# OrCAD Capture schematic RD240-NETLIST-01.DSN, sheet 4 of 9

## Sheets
4 6: size A3
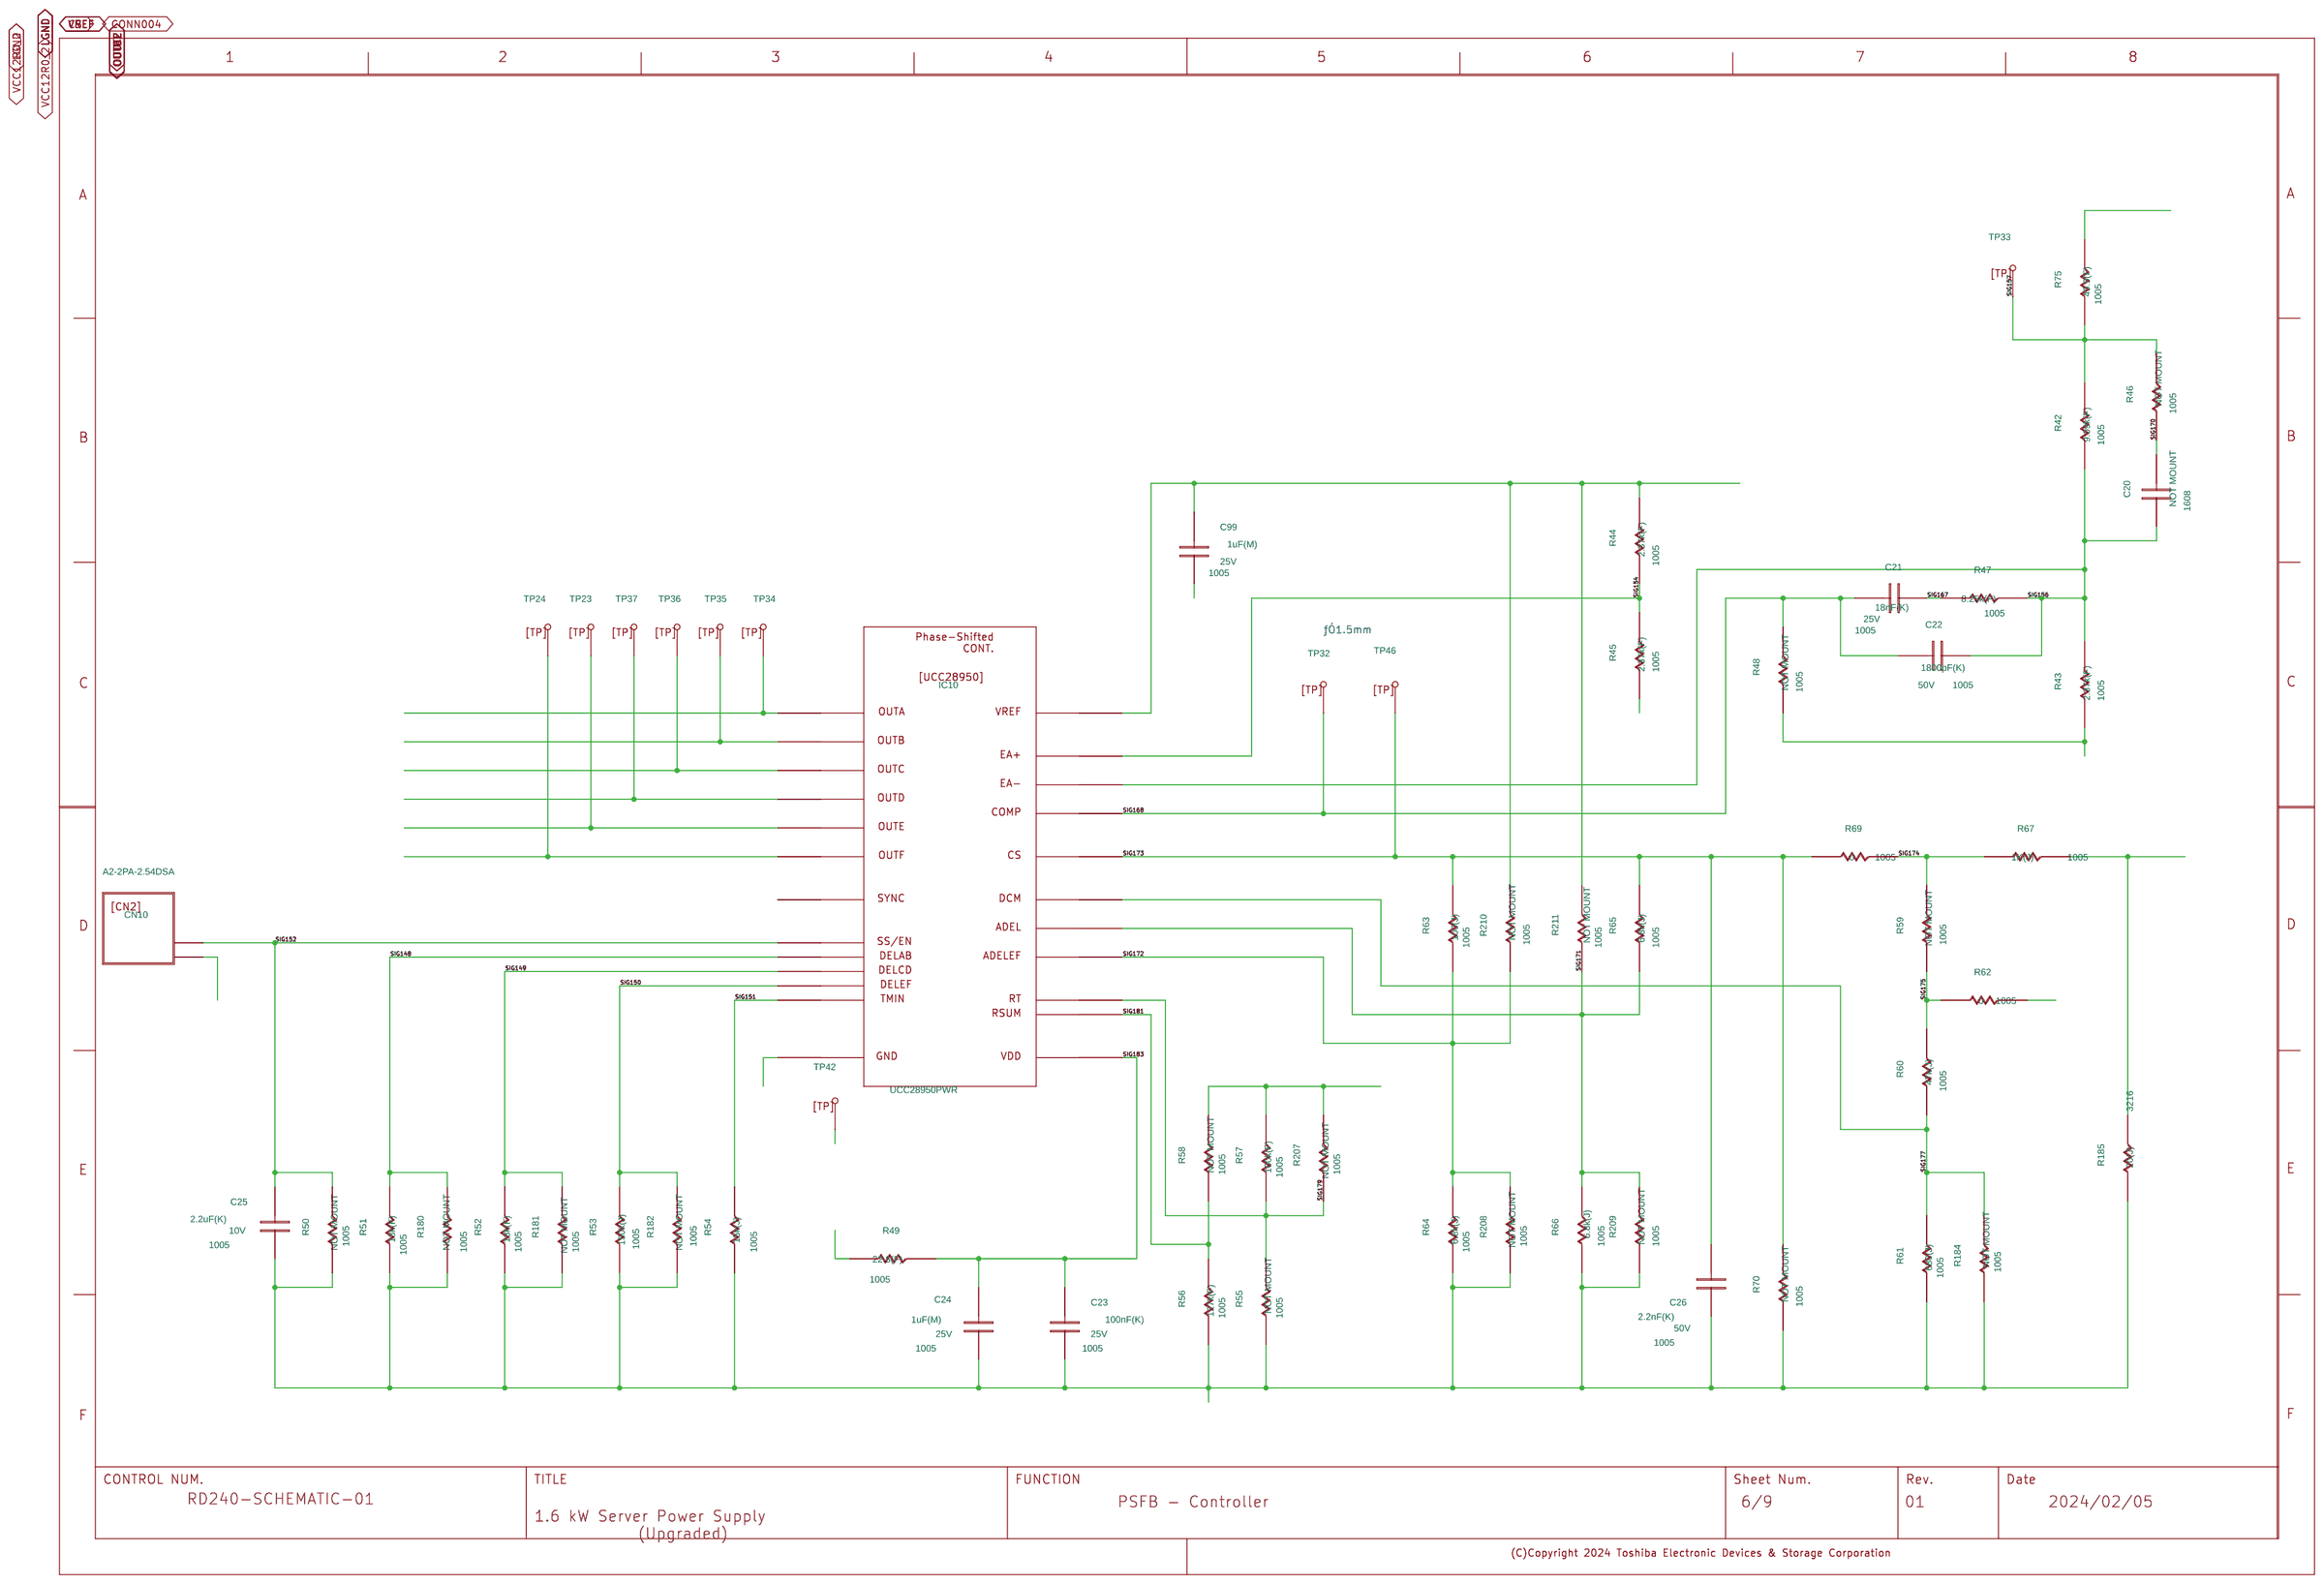
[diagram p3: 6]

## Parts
C20  C
C21  C
C22  C
C23  C
C24  C
C25  C
C26  C
C99  C
CN10  CN2
IC10  L28950
R42  R
R43  R
R44  R
R45  R
R46  R
R47  R
R48  R
R49  R
R50  R
R51  R
R52  R
R53  R
R54  R
R55  R
R56  R
R57  R
R58  R
R59  R
R60  R
R61  R
R62  R
R63  R
R64  R
R65  R
R66  R
R67  R
R69  R
R70  R
R75  R
R180  R
R181  R
R182  R
R184  R
R185  R
R207  R
R208  R
R209  R
R210  R
R211  R
TP23  TP
TP24  TP
TP32  TP
TP33  TP
TP34  TP
TP35  TP
TP36  TP
TP37  TP
TP42  TP
TP46  TP
U?#3  WAKU_DEF100

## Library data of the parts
C20 = C: ADSMODELNAME: s_GRM188B11E104KA01D; AUTHOR: sptcae13; CAPACITANCETOLE: K; CDMASTERCADCELG: KC0008; CHIPSIZE: 1608; COMP: PRT_48; COMPONENTTYPE: 4; DATE: 2024/01/31; FNLEADFREETHET1GT2GMCTH1: 3_1_N; GCOUNT: 1; INSTANCENAME: cmp137; MAXGCOUNT: 1; NOMINALCAPACITA: 100n; NOTMOUNT: NOT MOUNT; OUMECLASSIFICATION: ƒZƒ‰ƒ~ƒbƒNƒRƒ“ƒfƒ“ƒT; OUMEMAKER: MRT ºc»ì; OUMEMAKERKATAMEI: GRM188B11E104KA01D; PMPRODUCTSTYPEG: PC1; QUADMODEL: CON_100N; RATEDVOLTAGE: 25; SAVECOUNT: 0; SIZECODESMD: 1608; TEMPCHARACTERI2: B; TIME: 13:58:26; UPDATEDATE: 2024/01/31; UPDATETIME: 13:58:26; UPDATEUSER: sptcae13; VAL1: 100pF(J); VAL2: 50V
C21 = C: ADSCNVFLAG: ON; ADSCOMPONENTNAME: C_1005; ADSMODELNAME: s_GRM155B11E562KA01D; AUTHOR: sptcae13; CAPACITANCETOLE: K; CDMASTERCADCELG: KC0005; CHIPSIZE: 1005; COMP: PRT_52; COMPONENTTYPE: 4; DATE: 2024/01/31; FNLEADFREETHET1GT2GMCTH1: 2_0_N; GCOUNT: 1; ICX_PART_MODEL: CON_5.6N; INSTANCENAME: cmp42; MAKER: MURATA; MAXGCOUNT: 1; NOMINALCAPACITA: 5.6n; OUMECLASSIFICATION: ƒZƒ‰ƒ~ƒbƒNƒRƒ“ƒfƒ“ƒT; OUMEMAKER: MRT ºc»ì; OUMEMAKERKATAMEI: GRM155B11E562KA01D; PMPRODUCTSTYPEG: HD1; QUADMODEL: CON_5.6N; RATEDVOLTAGE: 25; SAVECOUNT: 0; SIZECODESMD: 1005; SQ_PART_MODEL: CON_5.6N; TEMPCHARACTERI2: B; TIME: 13:58:26; UPDATEDATE: 2024/01/31; UPDATETIME: 13:58:26; UPDATEUSER: sptcae13; VAL1: 18nF(K); VAL2: 25V; VAL3: GRM155R71E183KA61D
C22 = C: ADSCNVFLAG: ON; ADSCOMPONENTNAME: C_1005; ADSMODELNAME: s_C1005JB1H561KT; AUTHOR: sptcae13; CAPACITANCETOLE: K; CDMASTERCADCELG: KC0005; CHIPSIZE: 1005; COMP: PRT_52; COMPONENTTYPE: 4; DATE: 2024/01/31; FNLEADFREETHET1GT2GMCTH1: 2_0_N; GCOUNT: 1; ICX_PART_MODEL: CON_560P; INSTANCENAME: cmp43; MAKER: MURATA; MAXGCOUNT: 1; NOMINALCAPACITA: 560p; OUMECLASSIFICATION: ƒZƒ‰ƒ~ƒbƒNƒRƒ“ƒfƒ“ƒT; OUMEMAKER: TDK ‚s‚c‚j; OUMEMAKERKATAMEI: C1005JB1H561KT; PMPRODUCTSTYPEG: HD1-PC1; QUADMODEL: CON_560P; RATEDVOLTAGE: 50; SAVECOUNT: 0; SIZECODESMD: 1005; SQ_PART_MODEL: CON_560P; TEMPCHARACTERI2: B; TIME: 13:58:26; UPDATEDATE: 2024/01/31; UPDATETIME: 13:58:26; UPDATEUSER: sptcae13; VAL1: 1800pF(K); VAL2: 50V; VAL3: GRM155R71H182KA01D
C23 = C: ADSMODELNAME: s_GRM155R71E104KE14D; AUTHOR: sptcae13; CAPACITANCETOLE: K; CDMASTERCADCELG: KC0005; CHIPSIZE: 1005; COMP: PRT_52; COMPONENTTYPE: 4; DATE: 2024/01/31; FNLEADFREETHET1GT2GMCTH1: N_N_N; GCOUNT: 1; INSTANCENAME: cmp90; MAKER: TDK; MAXGCOUNT: 1; NOMINALCAPACITA: 100n; OUMECLASSIFICATION: ƒZƒ‰ƒ~ƒbƒNƒRƒ“ƒfƒ“ƒT; OUMEMAKER: MRT ºc»ì; OUMEMAKERKATAMEI: GRM155R71E104KE14D; QUADMODEL: CON_100N; RATEDVOLTAGE: 25; SAVECOUNT: 0; SIZECODESMD: 1005; TIME: 13:58:26; UPDATEDATE: 2024/01/31; UPDATETIME: 13:58:26; UPDATEUSER: sptcae13; VAL1: 100nF(K); VAL2: 25V; VAL3: C1005X7R1E104K050BB
C24 = C: ADSMODELNAME: s_GRM155B31E105KA12D; AUTHOR: sptcae13; CAPACITANCETOLE: K; CDMASTERCADCELG: KC0005; CHIPSIZE: 1005; COMP: PRT_52; COMPONENTTYPE: 4; DATE: 2024/01/31; FNLEADFREETHET1GT2GMCTH1: 3_0_N; GCOUNT: 1; INSTANCENAME: cmp91; MAKER: TDK; MAXGCOUNT: 1; NOMINALCAPACITA: 1u; OUMECLASSIFICATION: ƒZƒ‰ƒ~ƒbƒNƒRƒ“ƒfƒ“ƒT; OUMEMAKER: MRT ºc»ì; OUMEMAKERKATAMEI: GRM155B31E105KA12D; PMPRODUCTSTYPEG: HD1; QUADMODEL: CON_1U; RATEDVOLTAGE: 25; SAVECOUNT: 0; SIZECODESMD: 1005; TEMPCHARACTERI2: B; TIME: 13:58:26; UPDATEDATE: 2024/01/31; UPDATETIME: 13:58:26; UPDATEUSER: sptcae13; VAL1: 1uF(M); VAL2: 25V; VAL3: C1005X5R1E105M050BC
C25 = C: ADSMODELNAME: s_C1005X5R1E154KT000E; AUTHOR: sptcae13; CAPACITANCETOLE: K; CDMASTERCADCELG: KC0005; CHIPSIZE: 1005; COMP: PRT_52; COMPONENTTYPE: 4; DATE: 2024/01/31; FNLEADFREETHET1GT2GMCTH1: 3_0_N; GCOUNT: 1; INSTANCENAME: cmp10; MAKER: MURATA; MAXGCOUNT: 1; NOMINALCAPACITA: 150n; OUMECLASSIFICATION: ƒZƒ‰ƒ~ƒbƒNƒRƒ“ƒfƒ“ƒT; OUMEMAKER: TDK ‚s‚c‚j; OUMEMAKERKATAMEI: C1005X5R1E154KT000E; PMPRODUCTSTYPEG: HD1; QUADMODEL: CON_150N; RATEDVOLTAGE: 25; SAVECOUNT: 0; SIZECODESMD: 1005; TIME: 13:58:26; UPDATEDATE: 2024/01/31; UPDATETIME: 13:58:26; UPDATEUSER: sptcae13; VAL1: 2.2uF(K); VAL2: 10V; VAL3: GRM155C71A225KE11
C26 = C: ADSMODELNAME: s_UMK105BJ222KV_F; AUTHOR: sptcae13; CAPACITANCETOLE: K; CDMASTERCADCELG: KC0005; CHIPSIZE: 1005; COMP: PRT_52; COMPONENTTYPE: 4; DATE: 2024/01/31; FNLEADFREETHET1GT2GMCTH1: 2_0_N; GCOUNT: 1; INSTANCENAME: cmp118; MAKER: TDK; MAXGCOUNT: 1; NOMINALCAPACITA: 2.2n; OUMECLASSIFICATION: ƒZƒ‰ƒ~ƒbƒNƒRƒ“ƒfƒ“ƒT; OUMEMAKER: TYD ‘¾—z—U“d; OUMEMAKERKATAMEI: UMK105BJ222KV-F; PMPRODUCTSTYPEG: HD1-PC1; QUADMODEL: CON_2.2N; RATEDVOLTAGE: 50; SAVECOUNT: 0; SIZECODESMD: 1005; TEMPCHARACTERI2: B; TIME: 13:58:26; UPDATEDATE: 2024/01/31; UPDATETIME: 13:58:26; UPDATEUSER: sptcae13; VAL1: 2.2nF(K); VAL2: 50V; VAL3: UMK105BJ222KV-F
C99 = C: ADSMODELNAME: s_GRM155B31E105KA12D; AUTHOR: sptcae13; CAPACITANCETOLE: K; CDMASTERCADCELG: KC0005; CHIPSIZE: 1005; COMP: PRT_52; COMPONENTTYPE: 4; DATE: 2024/01/31; FNLEADFREETHET1GT2GMCTH1: 3_0_N; GCOUNT: 1; INSTANCENAME: cmp108; MAKER: TDK; MAXGCOUNT: 1; NOMINALCAPACITA: 1u; OUMECLASSIFICATION: ƒZƒ‰ƒ~ƒbƒNƒRƒ“ƒfƒ“ƒT; OUMEMAKER: MRT ºc»ì; OUMEMAKERKATAMEI: GRM155B31E105KA12D; PMPRODUCTSTYPEG: HD1; QUADMODEL: CON_1U; RATEDVOLTAGE: 25; SAVECOUNT: 0; SIZECODESMD: 1005; TEMPCHARACTERI2: B; TIME: 13:58:26; UPDATEDATE: 2024/01/31; UPDATETIME: 13:58:26; UPDATEUSER: sptcae13; VAL1: 1uF(M); VAL2: 25V; VAL3: C1005X5R1E105M050BC
CN10 = CN2: AUTHOR: sptcae13; COMP: PRT_56; COMPONENTTYPE: 4; DATE: 2024/01/31; INSTANCENAME: cmp117; MAKER: HIROSE; SAVECOUNT: 0; TIME: 13:58:24; UPDATEDATE: 2024/01/31; UPDATETIME: 13:58:24; UPDATEUSER: sptcae13; VAL3: A2-2PA-2.54DSA
IC10 = L28950: COMP: PRT_16; COMPONENTTYPE: 4; INSTANCENAME: cmp9; MAKER: TEXAS; VAL3: UCC28950PWR
R42 = R: ADSMODELNAME: s_RC0402FR_071KL; ALLGREEN: 0:O[; CDMASTERCADCELG: KC0005; CHIPSIZE: 1608; COMPONENTTYPE: 4; FNAPPROVALRESUG: B:i(GREEN); FNCANCELLATIONG: 0:Žg—p‰Â; FNENVIRONMANTRG: 1:gpL(K§ÎÛO); FNLEADFREETHET1GT2GMCTH1: 2_2_N; GANSWERREV: 8; GCOUNT: 1; INSTANCENAME: cmp23; MAKER: PANASONIC; MAXGCOUNT: 1; MOUNTINGFORMSMD: SMD; NOMINALRESISTAN: 1K; OUMECLASSIFICATION: \ÊÀpÅèïRí; OUMEMAKER: YGO ƒ„ƒQƒI; OUMEMAKERKATAMEI: RC0402FR-071KL; PMPRODUCTSTYPEG: HD1; POWERRATING: 63m; QUADMODEL: RES_1K; RESISTANCETOLER: F; SAVECOUNT: 0; SIZECODESMD: 1005; VAL1: 9.09k(F); VAL2: 63mW; VAL3: ERJ2RKF9091X
R43 = R: ADSMODELNAME: s_RC0402FR_071KL; ALLGREEN: 0:O[; CDMASTERCADCELG: KC0005; CHIPSIZE: 1608; COMPONENTTYPE: 4; FNAPPROVALRESUG: B:i(GREEN); FNCANCELLATIONG: 0:Žg—p‰Â; FNENVIRONMANTRG: 1:gpL(K§ÎÛO); FNLEADFREETHET1GT2GMCTH1: 2_2_N; GANSWERREV: 8; GCOUNT: 1; INSTANCENAME: cmp138; MAKER: PANASONIC; MAXGCOUNT: 1; MOUNTINGFORMSMD: SMD; NOMINALRESISTAN: 1K; OUMECLASSIFICATION: \ÊÀpÅèïRí; OUMEMAKER: YGO ƒ„ƒQƒI; OUMEMAKERKATAMEI: RC0402FR-071KL; PMPRODUCTSTYPEG: HD1; POWERRATING: 63m; QUADMODEL: RES_1K; RESISTANCETOLER: F; SAVECOUNT: 0; SIZECODESMD: 1005; VAL1: 2.37k(F); VAL2: 63mW; VAL3: ERJ2RKF2371X
R44 = R: ADSMODELNAME: s_RC0402FR_071KL; ALLGREEN: 0:O[; CDMASTERCADCELG: KC0005; CHIPSIZE: 1608; COMPONENTTYPE: 4; FNAPPROVALRESUG: B:i(GREEN); FNCANCELLATIONG: 0:Žg—p‰Â; FNENVIRONMANTRG: 1:gpL(K§ÎÛO); FNLEADFREETHET1GT2GMCTH1: 2_2_N; GANSWERREV: 8; GCOUNT: 1; INSTANCENAME: cmp129; MAKER: PANASONIC; MAXGCOUNT: 1; MOUNTINGFORMSMD: SMD; NOMINALRESISTAN: 1K; OUMECLASSIFICATION: \ÊÀpÅèïRí; OUMEMAKER: YGO ƒ„ƒQƒI; OUMEMAKERKATAMEI: RC0402FR-071KL; PMPRODUCTSTYPEG: HD1; POWERRATING: 63m; QUADMODEL: RES_1K; RESISTANCETOLER: F; SAVECOUNT: 0; SIZECODESMD: 1005; VAL1: 2.37k(F); VAL2: 63mW; VAL3: ERJ2RKF2371X
R45 = R: ADSMODELNAME: s_RC0402FR_071KL; ALLGREEN: 0:O[; CDMASTERCADCELG: KC0005; CHIPSIZE: 1608; COMPONENTTYPE: 4; FNAPPROVALRESUG: B:i(GREEN); FNCANCELLATIONG: 0:Žg—p‰Â; FNENVIRONMANTRG: 1:gpL(K§ÎÛO); FNLEADFREETHET1GT2GMCTH1: 2_2_N; GANSWERREV: 8; GCOUNT: 1; INSTANCENAME: cmp128; MAKER: PANASONIC; MAXGCOUNT: 1; MOUNTINGFORMSMD: SMD; NOMINALRESISTAN: 1K; OUMECLASSIFICATION: \ÊÀpÅèïRí; OUMEMAKER: YGO ƒ„ƒQƒI; OUMEMAKERKATAMEI: RC0402FR-071KL; PMPRODUCTSTYPEG: HD1; POWERRATING: 63m; QUADMODEL: RES_1K; RESISTANCETOLER: F; SAVECOUNT: 0; SIZECODESMD: 1005; VAL1: 2.37k(F); VAL2: 63mW; VAL3: ERJ2RKF2371X
R46 = R: ADSMODELNAME: s_RN73H1JTTD9091B10; CDMASTERCADCELG: KC0008; CHIPSIZE: 1608; COMPONENTTYPE: 4; FNLEADFREETHET1GT2GMCTH1: N_N_N; GCOUNT: 1; INSTANCENAME: cmp48; MAKER: KOA; MAXGCOUNT: 1; MOUNTINGFORMSMD: SMD; NOMINALRESISTAN: 9.09K; NOTMOUNT: NOT MOUNT; OUMECLASSIFICATION: \ÊÀpÅèïRí; OUMEMAKER: KOA R[A; OUMEMAKERKATAMEI: RN73H1JTTD9091B10; PMPRODUCTSTYPEG: DME; POWERRATING: 100m; QUADMODEL: RES_9.09K; RESISTANCETOLER: B; SAVECOUNT: 0; SIZECODESMD: 1005; VAL1: 0; VAL2: 63mW; VAL3: RK73Z1ETTP
R47 = R: ADSMODELNAME: s_RC0402FR_071KL; ALLGREEN: 0:O[; CDMASTERCADCELG: KC0005; CHIPSIZE: 1608; COMPONENTTYPE: 4; FNAPPROVALRESUG: B:i(GREEN); FNCANCELLATIONG: 0:Žg—p‰Â; FNENVIRONMANTRG: 1:gpL(K§ÎÛO); FNLEADFREETHET1GT2GMCTH1: 2_2_N; GANSWERREV: 8; GCOUNT: 1; INSTANCENAME: cmp141; MAKER: PANASONIC; MAXGCOUNT: 1; MOUNTINGFORMSMD: SMD; NOMINALRESISTAN: 1K; OUMECLASSIFICATION: \ÊÀpÅèïRí; OUMEMAKER: YGO ƒ„ƒQƒI; OUMEMAKERKATAMEI: RC0402FR-071KL; PMPRODUCTSTYPEG: HD1; POWERRATING: 63m; QUADMODEL: RES_1K; RESISTANCETOLER: F; SAVECOUNT: 0; SIZECODESMD: 1005; VAL1: 8.25k(F); VAL2: 63mW; VAL3: ERJ2RKF8251X
R48 = R: ADSMODELNAME: s_RK73Z1JTTD; CDMASTERCADCELG: KCK0203; CHIPSIZE: 1608; COMPONENTTYPE: 4; FNLEADFREETHET1GT2GMCTH1: 3_2_N; GCOUNT: 1; INSTANCENAME: cmp139; MAKER: KOA; MAXGCOUNT: 1; MOUNTINGFORMSMD: SMD; NOMINALRESISTAN: 0; NOTMOUNT: NOT MOUNT; OUMECLASSIFICATION: \ÊÀpÅèïRí; OUMEMAKER: KOA R[A; OUMEMAKERKATAMEI: RK73Z1JTTD; PMPRODUCTSTYPEG: DME-HD1-PC1; POWERRATING: 100m; QUADMODEL: RES_0; RESISTANCETOLER: X; SAVECOUNT: 0; SIZECODESMD: 1005; VAL1: 0; VAL2: 63mW; VAL3: RK73Z1ETTP
R49 = R: ADSMODELNAME: s_RC0402FR_071KL; ALLGREEN: 0:O[; CDMASTERCADCELG: KC0005; CHIPSIZE: 1608; COMPONENTTYPE: 4; FNAPPROVALRESUG: B:i(GREEN); FNCANCELLATIONG: 0:Žg—p‰Â; FNENVIRONMANTRG: 1:gpL(K§ÎÛO); FNLEADFREETHET1GT2GMCTH1: 2_2_N; GANSWERREV: 8; GCOUNT: 1; INSTANCENAME: cmp127; MAKER: PANASONIC; MAXGCOUNT: 1; MOUNTINGFORMSMD: SMD; NOMINALRESISTAN: 1K; OUMECLASSIFICATION: \ÊÀpÅèïRí; OUMEMAKER: YGO ƒ„ƒQƒI; OUMEMAKERKATAMEI: RC0402FR-071KL; PMPRODUCTSTYPEG: HD1; POWERRATING: 63m; QUADMODEL: RES_1K; RESISTANCETOLER: F; SAVECOUNT: 0; SIZECODESMD: 1005; VAL1: 22.6(F); VAL2: 63mW; VAL3: ERJ2RKF22R6X
R50 = R: ADSCNVFLAG: ON; ADSCOMPONENTNAME: R_1608; ADSMODELNAME: s_MCR03EZHF8253; CDMASTERCADCELG: DR802R; CHIPSIZE: 1608; COMPONENTTYPE: 4; FNLEADFREETHET1GT2GMCTH1: 3_1_N; GCOUNT: 1; ICX_PART_MODEL: RES_825K; INSTANCENAME: cmp11; MAKER: PANASONIC; MAXGCOUNT: 1; MOUNTINGFORMSMD: SMD; NOMINALRESISTAN: 825K; NOTMOUNT: NOT MOUNT; OUMECLASSIFICATION: \ÊÀpÅèïRí; OUMEMAKER: ROH [; OUMEMAKERKATAMEI: MCR03EZHF8253; POWERRATING: 100m; QUADMODEL: RES_825K; RESISTANCETOLER: F; SAVECOUNT: 0; SIZECODESMD: 1005; SQ_PART_MODEL: RES_825K; VAL1: 825(F); VAL2: 63mW; VAL3: ERJ2RKF8253X
R51 = R: ADSMODELNAME: s_RC0402FR_071KL; ALLGREEN: 0:O[; CDMASTERCADCELG: KC0005; CHIPSIZE: 1608; COMPONENTTYPE: 4; FNAPPROVALRESUG: B:i(GREEN); FNCANCELLATIONG: 0:Žg—p‰Â; FNENVIRONMANTRG: 1:gpL(K§ÎÛO); FNLEADFREETHET1GT2GMCTH1: 2_2_N; GANSWERREV: 8; GCOUNT: 1; INSTANCENAME: cmp120; MAKER: KOA; MAXGCOUNT: 1; MOUNTINGFORMSMD: SMD; NOMINALRESISTAN: 1K; OUMECLASSIFICATION: \ÊÀpÅèïRí; OUMEMAKER: YGO ƒ„ƒQƒI; OUMEMAKERKATAMEI: RC0402FR-071KL; PMPRODUCTSTYPEG: HD1; POWERRATING: 63m; QUADMODEL: RES_1K; RESISTANCETOLER: F; SAVECOUNT: 0; SIZECODESMD: 1005; VAL1: 18k(F); VAL2: 63mW; VAL3: RK73H1ETTP1802F
R52 = R: ADSMODELNAME: s_RC0402FR_071KL; ALLGREEN: 0:O[; CDMASTERCADCELG: KC0005; CHIPSIZE: 1608; COMPONENTTYPE: 4; FNAPPROVALRESUG: B:i(GREEN); FNCANCELLATIONG: 0:Žg—p‰Â; FNENVIRONMANTRG: 1:gpL(K§ÎÛO); FNLEADFREETHET1GT2GMCTH1: 2_2_N; GANSWERREV: 8; GCOUNT: 1; INSTANCENAME: cmp121; MAKER: KOA; MAXGCOUNT: 1; MOUNTINGFORMSMD: SMD; NOMINALRESISTAN: 1K; OUMECLASSIFICATION: \ÊÀpÅèïRí; OUMEMAKER: YGO ƒ„ƒQƒI; OUMEMAKERKATAMEI: RC0402FR-071KL; PMPRODUCTSTYPEG: HD1; POWERRATING: 63m; QUADMODEL: RES_1K; RESISTANCETOLER: F; SAVECOUNT: 0; SIZECODESMD: 1005; VAL1: 18k(F); VAL2: 63mW; VAL3: RK73H1ETTP1802F
R53 = R: ADSMODELNAME: s_RC0402FR_071KL; ALLGREEN: 0:O[; CDMASTERCADCELG: KC0005; CHIPSIZE: 1608; COMPONENTTYPE: 4; FNAPPROVALRESUG: B:i(GREEN); FNCANCELLATIONG: 0:Žg—p‰Â; FNENVIRONMANTRG: 1:gpL(K§ÎÛO); FNLEADFREETHET1GT2GMCTH1: 2_2_N; GANSWERREV: 8; GCOUNT: 1; INSTANCENAME: cmp125; MAKER: KOA; MAXGCOUNT: 1; MOUNTINGFORMSMD: SMD; NOMINALRESISTAN: 1K; OUMECLASSIFICATION: \ÊÀpÅèïRí; OUMEMAKER: YGO ƒ„ƒQƒI; OUMEMAKERKATAMEI: RC0402FR-071KL; PMPRODUCTSTYPEG: HD1; POWERRATING: 63m; QUADMODEL: RES_1K; RESISTANCETOLER: F; SAVECOUNT: 0; SIZECODESMD: 1005; VAL1: 150k(J); VAL2: 63mW; VAL3: RK73B1ETTP154J
R54 = R: ADSCNVFLAG: ON; ADSCOMPONENTNAME: R_1608; ADSMODELNAME: s_RC0402FR_071KL; ALLGREEN: 0:O[; CDMASTERCADCELG: KC0005; CHIPSIZE: 1608; COMPONENTTYPE: 4; FNAPPROVALRESUG: B:i(GREEN); FNCANCELLATIONG: 0:Žg—p‰Â; FNENVIRONMANTRG: 1:gpL(K§ÎÛO); FNLEADFREETHET1GT2GMCTH1: 2_2_N; GANSWERREV: 8; GCOUNT: 1; ICX_PART_MODEL: RES_15K; INSTANCENAME: cmp126; MAKER: KOA; MAXGCOUNT: 1; MOUNTINGFORMSMD: SMD; NOMINALRESISTAN: 1K; OUMECLASSIFICATION: \ÊÀpÅèïRí; OUMEMAKER: YGO ƒ„ƒQƒI; OUMEMAKERKATAMEI: RC0402FR-071KL; PMPRODUCTSTYPEG: HD1; POWERRATING: 63m; QUADMODEL: RES_1K; RESISTANCETOLER: F; SAVECOUNT: 0; SIZECODESMD: 1005; SQ_PART_MODEL: RES_15K; VAL1: 15k(J); VAL2: 63mW; VAL3: RK73B1ETTP153J
R55 = R: ADSMODELNAME: s_RK73Z1JTTD; CDMASTERCADCELG: KCK0203; CHIPSIZE: 1608; COMPONENTTYPE: 4; FNLEADFREETHET1GT2GMCTH1: 3_2_N; GCOUNT: 1; INSTANCENAME: cmp151; MAKER: KOA; MAXGCOUNT: 1; MOUNTINGFORMSMD: SMD; NOMINALRESISTAN: 0; NOTMOUNT: NOT MOUNT; OUMECLASSIFICATION: \ÊÀpÅèïRí; OUMEMAKER: KOA R[A; OUMEMAKERKATAMEI: RK73Z1JTTD; PMPRODUCTSTYPEG: DME-HD1-PC1; POWERRATING: 100m; QUADMODEL: RES_0; RESISTANCETOLER: X; SAVECOUNT: 0; SIZECODESMD: 1005; VAL1: 0; VAL2: 63mW; VAL3: RK73Z1ETTP
R56 = R: ADSMODELNAME: s_RC0402FR_071KL; ALLGREEN: 0:O[; CDMASTERCADCELG: KC0005; CHIPSIZE: 1608; COMPONENTTYPE: 4; FNAPPROVALRESUG: B:i(GREEN); FNCANCELLATIONG: 0:Žg—p‰Â; FNENVIRONMANTRG: 1:gpL(K§ÎÛO); FNLEADFREETHET1GT2GMCTH1: 2_2_N; GANSWERREV: 8; GCOUNT: 1; INSTANCENAME: cmp150; MAKER: PANASONIC; MAXGCOUNT: 1; MOUNTINGFORMSMD: SMD; NOMINALRESISTAN: 1K; OUMECLASSIFICATION: \ÊÀpÅèïRí; OUMEMAKER: YGO ƒ„ƒQƒI; OUMEMAKERKATAMEI: RC0402FR-071KL; PMPRODUCTSTYPEG: HD1; POWERRATING: 63m; QUADMODEL: RES_1K; RESISTANCETOLER: F; SAVECOUNT: 0; SIZECODESMD: 1005; VAL1: 127k(F); VAL2: 63mW; VAL3: ERJ2RKF1273X
R57 = R: ADSMODELNAME: s_RC0402FR_071KL; ALLGREEN: 0:O[; CDMASTERCADCELG: KC0005; CHIPSIZE: 1608; COMPONENTTYPE: 4; FNAPPROVALRESUG: B:i(GREEN); FNCANCELLATIONG: 0:Žg—p‰Â; FNENVIRONMANTRG: 1:gpL(K§ÎÛO); FNLEADFREETHET1GT2GMCTH1: 2_2_N; GANSWERREV: 8; GCOUNT: 1; INSTANCENAME: cmp119; MAKER: PANASONIC; MAXGCOUNT: 1; MOUNTINGFORMSMD: SMD; NOMINALRESISTAN: 1K; OUMECLASSIFICATION: \ÊÀpÅèïRí; OUMEMAKER: YGO ƒ„ƒQƒI; OUMEMAKERKATAMEI: RC0402FR-071KL; PMPRODUCTSTYPEG: HD1; POWERRATING: 63m; QUADMODEL: RES_1K; RESISTANCETOLER: F; SAVECOUNT: 0; SIZECODESMD: 1005; VAL1: 100k(F); VAL2: 63mW; VAL3: RK73H1ERTTP1003F
R58 = R: ADSMODELNAME: s_RK73Z1JTTD; CDMASTERCADCELG: KCK0203; CHIPSIZE: 1608; COMPONENTTYPE: 4; FNLEADFREETHET1GT2GMCTH1: 3_2_N; GCOUNT: 1; INSTANCENAME: cmp149; MAKER: KOA; MAXGCOUNT: 1; MOUNTINGFORMSMD: SMD; NOMINALRESISTAN: 0; NOTMOUNT: NOT MOUNT; OUMECLASSIFICATION: \ÊÀpÅèïRí; OUMEMAKER: KOA R[A; OUMEMAKERKATAMEI: RK73Z1JTTD; PMPRODUCTSTYPEG: DME-HD1-PC1; POWERRATING: 100m; QUADMODEL: RES_0; RESISTANCETOLER: X; SAVECOUNT: 0; SIZECODESMD: 1005; VAL1: 0; VAL2: 63mW; VAL3: RK73Z1ETTP
R59 = R: ADSMODELNAME: s_RK73Z1JTTD; CDMASTERCADCELG: KCK0203; CHIPSIZE: 1608; COMPONENTTYPE: 4; FNLEADFREETHET1GT2GMCTH1: 3_2_N; GCOUNT: 1; INSTANCENAME: cmp142; MAKER: KOA; MAXGCOUNT: 1; MOUNTINGFORMSMD: SMD; NOMINALRESISTAN: 0; NOTMOUNT: NOT MOUNT; OUMECLASSIFICATION: \ÊÀpÅèïRí; OUMEMAKER: KOA R[A; OUMEMAKERKATAMEI: RK73Z1JTTD; PMPRODUCTSTYPEG: DME-HD1-PC1; POWERRATING: 100m; QUADMODEL: RES_0; RESISTANCETOLER: X; SAVECOUNT: 0; SIZECODESMD: 1005; VAL1: 0; VAL2: 63mW; VAL3: RK73Z1ETTP
R60 = R: ADSMODELNAME: s_RC0402FR_071KL; ALLGREEN: 0:O[; CDMASTERCADCELG: KC0005; CHIPSIZE: 1608; COMPONENTTYPE: 4; FNAPPROVALRESUG: B:i(GREEN); FNCANCELLATIONG: 0:Žg—p‰Â; FNENVIRONMANTRG: 1:gpL(K§ÎÛO); FNLEADFREETHET1GT2GMCTH1: 2_2_N; GANSWERREV: 8; GCOUNT: 1; INSTANCENAME: cmp145; MAKER: KOA; MAXGCOUNT: 1; MOUNTINGFORMSMD: SMD; NOMINALRESISTAN: 1K; OUMECLASSIFICATION: \ÊÀpÅèïRí; OUMEMAKER: YGO ƒ„ƒQƒI; OUMEMAKERKATAMEI: RC0402FR-071KL; PMPRODUCTSTYPEG: HD1; POWERRATING: 63m; QUADMODEL: RES_1K; RESISTANCETOLER: F; SAVECOUNT: 0; SIZECODESMD: 1005; VAL1: 47k(J); VAL2: 63mW; VAL3: RK73B1ETTP473J
R61 = R: ADSMODELNAME: s_RC0402FR_071KL; ALLGREEN: 0:O[; CDMASTERCADCELG: KC0005; CHIPSIZE: 1608; COMPONENTTYPE: 4; FNAPPROVALRESUG: B:i(GREEN); FNCANCELLATIONG: 0:Žg—p‰Â; FNENVIRONMANTRG: 1:gpL(K§ÎÛO); FNLEADFREETHET1GT2GMCTH1: 2_2_N; GANSWERREV: 8; GCOUNT: 1; INSTANCENAME: cmp146; MAKER: KOA; MAXGCOUNT: 1; MOUNTINGFORMSMD: SMD; NOMINALRESISTAN: 1K; OUMECLASSIFICATION: \ÊÀpÅèïRí; OUMEMAKER: YGO ƒ„ƒQƒI; OUMEMAKERKATAMEI: RC0402FR-071KL; PMPRODUCTSTYPEG: HD1; POWERRATING: 63m; QUADMODEL: RES_1K; RESISTANCETOLER: F; SAVECOUNT: 0; SIZECODESMD: 1005; VAL1: 680(J); VAL2: 63mW; VAL3: ERJ2GEJ681X
R62 = R: ADSMODELNAME: s_RC0402FR_071KL; ALLGREEN: 0:O[; CDMASTERCADCELG: KC0005; CHIPSIZE: 1608; COMPONENTTYPE: 4; FNAPPROVALRESUG: B:i(GREEN); FNCANCELLATIONG: 0:Žg—p‰Â; FNENVIRONMANTRG: 1:gpL(K§ÎÛO); FNLEADFREETHET1GT2GMCTH1: 2_2_N; GANSWERREV: 8; GCOUNT: 1; INSTANCENAME: cmp143; MAKER: KOA; MAXGCOUNT: 1; MOUNTINGFORMSMD: SMD; NOMINALRESISTAN: 1K; OUMECLASSIFICATION: \ÊÀpÅèïRí; OUMEMAKER: YGO ƒ„ƒQƒI; OUMEMAKERKATAMEI: RC0402FR-071KL; PMPRODUCTSTYPEG: HD1; POWERRATING: 63m; QUADMODEL: RES_1K; RESISTANCETOLER: F; SAVECOUNT: 0; SIZECODESMD: 1005; VAL1: 0; VAL2: 63mW; VAL3: RK73Z1ETTP
R63 = R: ADSCOMPONENTNAME: R_1005; ADSMODELNAME: s_RC0402FR_071KL; ALLGREEN: 0:O[; CDMASTERCADCELG: KC0005; CHIPSIZE: 1608; COMPONENTTYPE: 4; FNAPPROVALRESUG: B:i(GREEN); FNCANCELLATIONG: 0:Žg—p‰Â; FNENVIRONMANTRG: 1:gpL(K§ÎÛO); FNLEADFREETHET1GT2GMCTH1: 2_2_N; GANSWERREV: 8; GCOUNT: 1; INSTANCENAME: cmp50; MAKER: KOA; MAXGCOUNT: 1; MOUNTINGFORMSMD: SMD; NOMINALRESISTAN: 1K; OUMECLASSIFICATION: \ÊÀpÅèïRí; OUMEMAKER: YGO ƒ„ƒQƒI; OUMEMAKERKATAMEI: RC0402FR-071KL; PMPRODUCTSTYPEG: HD1; POWERRATING: 63m; QUADMODEL: RES_1K; RESISTANCETOLER: F; SAVECOUNT: 0; SIZECODESMD: 1005; VAL1: 100(J); VAL2: 63mW; VAL3: RK73K1ETP101J
R64 = R: ADSMODELNAME: s_RC0402FR_071KL; ALLGREEN: 0:O[; CDMASTERCADCELG: KC0005; CHIPSIZE: 1608; COMPONENTTYPE: 4; FNAPPROVALRESUG: B:i(GREEN); FNCANCELLATIONG: 0:Žg—p‰Â; FNENVIRONMANTRG: 1:gpL(K§ÎÛO); FNLEADFREETHET1GT2GMCTH1: 2_2_N; GANSWERREV: 8; GCOUNT: 1; INSTANCENAME: cmp130; MAKER: KOA; MAXGCOUNT: 1; MOUNTINGFORMSMD: SMD; NOMINALRESISTAN: 1K; OUMECLASSIFICATION: \ÊÀpÅèïRí; OUMEMAKER: YGO ƒ„ƒQƒI; OUMEMAKERKATAMEI: RC0402FR-071KL; PMPRODUCTSTYPEG: HD1; POWERRATING: 63m; QUADMODEL: RES_1K; RESISTANCETOLER: F; SAVECOUNT: 0; SIZECODESMD: 1005; VAL1: 6.8k(J); VAL2: 63mW; VAL3: RK73B1ETTP682J
R65 = R: ADSCOMPONENTNAME: R_1005; ADSMODELNAME: s_RC0402FR_071KL; ALLGREEN: 0:O[; CDMASTERCADCELG: KC0005; CHIPSIZE: 1608; COMPONENTTYPE: 4; FNAPPROVALRESUG: B:i(GREEN); FNCANCELLATIONG: 0:Žg—p‰Â; FNENVIRONMANTRG: 1:gpL(K§ÎÛO); FNLEADFREETHET1GT2GMCTH1: 2_2_N; GANSWERREV: 8; GCOUNT: 1; INSTANCENAME: cmp51; MAKER: KOA; MAXGCOUNT: 1; MOUNTINGFORMSMD: SMD; NOMINALRESISTAN: 1K; OUMECLASSIFICATION: \ÊÀpÅèïRí; OUMEMAKER: YGO ƒ„ƒQƒI; OUMEMAKERKATAMEI: RC0402FR-071KL; PMPRODUCTSTYPEG: HD1; POWERRATING: 63m; QUADMODEL: RES_1K; RESISTANCETOLER: F; SAVECOUNT: 0; SIZECODESMD: 1005; VAL1: 6.8k(J); VAL2: 63mW; VAL3: RK73B1ETTP682J
R66 = R: ADSMODELNAME: s_RC0402FR_071KL; ALLGREEN: 0:O[; CDMASTERCADCELG: KC0005; CHIPSIZE: 1608; COMPONENTTYPE: 4; FNAPPROVALRESUG: B:i(GREEN); FNCANCELLATIONG: 0:Žg—p‰Â; FNENVIRONMANTRG: 1:gpL(K§ÎÛO); FNLEADFREETHET1GT2GMCTH1: 2_2_N; GANSWERREV: 8; GCOUNT: 1; INSTANCENAME: cmp131; MAKER: KOA; MAXGCOUNT: 1; MOUNTINGFORMSMD: SMD; NOMINALRESISTAN: 1K; OUMECLASSIFICATION: \ÊÀpÅèïRí; OUMEMAKER: YGO ƒ„ƒQƒI; OUMEMAKERKATAMEI: RC0402FR-071KL; PMPRODUCTSTYPEG: HD1; POWERRATING: 63m; QUADMODEL: RES_1K; RESISTANCETOLER: F; SAVECOUNT: 0; SIZECODESMD: 1005; VAL1: 6.8k(J); VAL2: 63mW; VAL3: RK73B1ETTP682J
R67 = R: ADSMODELNAME: s_RC0402FR_071KL; ALLGREEN: 0:O[; CDMASTERCADCELG: KC0005; CHIPSIZE: 1608; COMPONENTTYPE: 4; FNAPPROVALRESUG: B:i(GREEN); FNCANCELLATIONG: 0:Žg—p‰Â; FNENVIRONMANTRG: 1:gpL(K§ÎÛO); FNLEADFREETHET1GT2GMCTH1: 2_2_N; GANSWERREV: 8; GCOUNT: 1; INSTANCENAME: cmp144; MAKER: KOA; MAXGCOUNT: 1; MOUNTINGFORMSMD: SMD; NOMINALRESISTAN: 1K; OUMECLASSIFICATION: \ÊÀpÅèïRí; OUMEMAKER: YGO ƒ„ƒQƒI; OUMEMAKERKATAMEI: RC0402FR-071KL; PMPRODUCTSTYPEG: HD1; POWERRATING: 63m; QUADMODEL: RES_1K; RESISTANCETOLER: F; SAVECOUNT: 0; SIZECODESMD: 1005; VAL1: 1K(J); VAL2: 63mW; VAL3: RK73K1ETP102J
R69 = R: ADSCNVFLAG: ON; ADSCOMPONENTNAME: R_1608; ADSMODELNAME: s_RC0402FR_071KL; ALLGREEN: 0:O[; CDMASTERCADCELG: KC0005; CHIPSIZE: 1608; COMPONENTTYPE: 4; FNAPPROVALRESUG: B:i(GREEN); FNCANCELLATIONG: 0:Žg—p‰Â; FNENVIRONMANTRG: 1:gpL(K§ÎÛO); FNLEADFREETHET1GT2GMCTH1: 2_2_N; GANSWERREV: 8; GCOUNT: 1; ICX_PART_MODEL: RES_0; INSTANCENAME: cmp140; MAKER: KOA; MAXGCOUNT: 1; MOUNTINGFORMSMD: SMD; NOMINALRESISTAN: 1K; OUMECLASSIFICATION: \ÊÀpÅèïRí; OUMEMAKER: YGO ƒ„ƒQƒI; OUMEMAKERKATAMEI: RC0402FR-071KL; PMPRODUCTSTYPEG: HD1; POWERRATING: 63m; QUADMODEL: RES_1K; RESISTANCETOLER: F; SAVECOUNT: 0; SIZECODESMD: 1005; SQ_PART_MODEL: RES_0; VAL1: 0; VAL2: 63mW; VAL3: RK73Z1ETTP
R70 = R: ADSMODELNAME: s_RK73Z1JTTD; CDMASTERCADCELG: KCK0203; CHIPSIZE: 1608; COMPONENTTYPE: 4; FNLEADFREETHET1GT2GMCTH1: 3_2_N; GCOUNT: 1; INSTANCENAME: cmp134; MAKER: KOA; MAXGCOUNT: 1; MOUNTINGFORMSMD: SMD; NOMINALRESISTAN: 0; NOTMOUNT: NOT MOUNT; OUMECLASSIFICATION: \ÊÀpÅèïRí; OUMEMAKER: KOA R[A; OUMEMAKERKATAMEI: RK73Z1JTTD; PMPRODUCTSTYPEG: DME-HD1-PC1; POWERRATING: 100m; QUADMODEL: RES_0; RESISTANCETOLER: X; SAVECOUNT: 0; SIZECODESMD: 1005; VAL1: 0; VAL2: 63mW; VAL3: RK73Z1ETTP
R75 = R: ADSMODELNAME: s_RC0402FR_071KL; ALLGREEN: 0:O[; CDMASTERCADCELG: KC0005; CHIPSIZE: 1608; COMPONENTTYPE: 4; FNAPPROVALRESUG: B:i(GREEN); FNCANCELLATIONG: 0:Žg—p‰Â; FNENVIRONMANTRG: 1:gpL(K§ÎÛO); FNLEADFREETHET1GT2GMCTH1: 2_2_N; GANSWERREV: 8; GCOUNT: 1; INSTANCENAME: cmp135; MAKER: KOA; MAXGCOUNT: 1; MOUNTINGFORMSMD: SMD; NOMINALRESISTAN: 1K; OUMECLASSIFICATION: \ÊÀpÅèïRí; OUMEMAKER: YGO ƒ„ƒQƒI; OUMEMAKERKATAMEI: RC0402FR-071KL; PMPRODUCTSTYPEG: HD1; POWERRATING: 63m; QUADMODEL: RES_1K; RESISTANCETOLER: F; SAVECOUNT: 0; SIZECODESMD: 1005; VAL1: 49.9(F); VAL2: 63mW; VAL3: ERJ2RKF49R9X
R180 = R: ADSMODELNAME: s_RK73Z1JTTD; CDMASTERCADCELG: KCK0203; CHIPSIZE: 1608; COMPONENTTYPE: 4; FNLEADFREETHET1GT2GMCTH1: 3_2_N; GCOUNT: 1; INSTANCENAME: cmp122; MAKER: KOA; MAXGCOUNT: 1; MOUNTINGFORMSMD: SMD; NOMINALRESISTAN: 0; NOTMOUNT: NOT MOUNT; OUMECLASSIFICATION: \ÊÀpÅèïRí; OUMEMAKER: KOA R[A; OUMEMAKERKATAMEI: RK73Z1JTTD; PMPRODUCTSTYPEG: DME-HD1-PC1; POWERRATING: 100m; QUADMODEL: RES_0; RESISTANCETOLER: X; SAVECOUNT: 0; SIZECODESMD: 1005; VAL1: 0; VAL2: 63mW; VAL3: RK73Z1ETTP
R181 = R: ADSMODELNAME: s_RK73Z1JTTD; CDMASTERCADCELG: KCK0203; CHIPSIZE: 1608; COMPONENTTYPE: 4; FNLEADFREETHET1GT2GMCTH1: 3_2_N; GCOUNT: 1; INSTANCENAME: cmp123; MAKER: KOA; MAXGCOUNT: 1; MOUNTINGFORMSMD: SMD; NOMINALRESISTAN: 0; NOTMOUNT: NOT MOUNT; OUMECLASSIFICATION: \ÊÀpÅèïRí; OUMEMAKER: KOA R[A; OUMEMAKERKATAMEI: RK73Z1JTTD; PMPRODUCTSTYPEG: DME-HD1-PC1; POWERRATING: 100m; QUADMODEL: RES_0; RESISTANCETOLER: X; SAVECOUNT: 0; SIZECODESMD: 1005; VAL1: 0; VAL2: 63mW; VAL3: RK73Z1ETTP
R182 = R: ADSMODELNAME: s_RK73Z1JTTD; CDMASTERCADCELG: KCK0203; CHIPSIZE: 1608; COMPONENTTYPE: 4; FNLEADFREETHET1GT2GMCTH1: 3_2_N; GCOUNT: 1; INSTANCENAME: cmp124; MAKER: KOA; MAXGCOUNT: 1; MOUNTINGFORMSMD: SMD; NOMINALRESISTAN: 0; NOTMOUNT: NOT MOUNT; OUMECLASSIFICATION: \ÊÀpÅèïRí; OUMEMAKER: KOA R[A; OUMEMAKERKATAMEI: RK73Z1JTTD; PMPRODUCTSTYPEG: DME-HD1-PC1; POWERRATING: 100m; QUADMODEL: RES_0; RESISTANCETOLER: X; SAVECOUNT: 0; SIZECODESMD: 1005; VAL1: 0; VAL2: 63mW; VAL3: RK73Z1ETTP
R184 = R: ADSMODELNAME: s_RK73Z1JTTD; CDMASTERCADCELG: KCK0203; CHIPSIZE: 1608; COMPONENTTYPE: 4; FNLEADFREETHET1GT2GMCTH1: 3_2_N; GCOUNT: 1; INSTANCENAME: cmp147; MAKER: KOA; MAXGCOUNT: 1; MOUNTINGFORMSMD: SMD; NOMINALRESISTAN: 0; NOTMOUNT: NOT MOUNT; OUMECLASSIFICATION: \ÊÀpÅèïRí; OUMEMAKER: KOA R[A; OUMEMAKERKATAMEI: RK73Z1JTTD; PMPRODUCTSTYPEG: DME-HD1-PC1; POWERRATING: 100m; QUADMODEL: RES_0; RESISTANCETOLER: X; SAVECOUNT: 0; SIZECODESMD: 1005; VAL1: 0; VAL2: 63mW; VAL3: RK73Z1ETTP
R185 = R: ADSMODELNAME: s_MCR18EZHJ220; CDMASTERCADCELG: DR901A; CHIPSIZE: 3216; COMPONENTTYPE: 4; FNLEADFREETHET1GT2GMCTH1: N_N_N; GCOUNT: 1; INSTANCENAME: cmp148; MAKER: PANASONIC; MAXGCOUNT: 1; MOUNTINGFORMSMD: SMD; NOMINALRESISTAN: 22; OUMECLASSIFICATION: \ÊÀpÅèïRí; OUMEMAKER: ROH [; OUMEMAKERKATAMEI: MCR18EZHJ220; POWERRATING: 250m; QUADMODEL: RES_22; RESISTANCETOLER: J; SAVECOUNT: 0; SIZECODESMD: 3216; VAL1: 20(J); VAL2: 250mW; VAL3: ERJ-8GEYJ200V
R207 = R: ADSMODELNAME: s_RK73Z1JTTD; CDMASTERCADCELG: KCK0203; CHIPSIZE: 1608; COMPONENTTYPE: 4; FNLEADFREETHET1GT2GMCTH1: 3_2_N; GCOUNT: 1; INSTANCENAME: cmp152; MAKER: KOA; MAXGCOUNT: 1; MOUNTINGFORMSMD: SMD; NOMINALRESISTAN: 0; NOTMOUNT: NOT MOUNT; OUMECLASSIFICATION: \ÊÀpÅèïRí; OUMEMAKER: KOA R[A; OUMEMAKERKATAMEI: RK73Z1JTTD; PMPRODUCTSTYPEG: DME-HD1-PC1; POWERRATING: 100m; QUADMODEL: RES_0; RESISTANCETOLER: X; SAVECOUNT: 0; SIZECODESMD: 1005; VAL1: 0; VAL2: 63mW; VAL3: RK73Z1ETTP
R208 = R: ADSMODELNAME: s_RK73Z1JTTD; CDMASTERCADCELG: KCK0203; CHIPSIZE: 1608; COMPONENTTYPE: 4; FNLEADFREETHET1GT2GMCTH1: 3_2_N; GCOUNT: 1; INSTANCENAME: cmp133; MAKER: KOA; MAXGCOUNT: 1; MOUNTINGFORMSMD: SMD; NOMINALRESISTAN: 0; NOTMOUNT: NOT MOUNT; OUMECLASSIFICATION: \ÊÀpÅèïRí; OUMEMAKER: KOA R[A; OUMEMAKERKATAMEI: RK73Z1JTTD; PMPRODUCTSTYPEG: DME-HD1-PC1; POWERRATING: 100m; QUADMODEL: RES_0; RESISTANCETOLER: X; SAVECOUNT: 0; SIZECODESMD: 1005; VAL1: 0; VAL2: 63mW; VAL3: RK73Z1ETTP
R209 = R: ADSMODELNAME: s_RK73Z1JTTD; CDMASTERCADCELG: KCK0203; CHIPSIZE: 1608; COMPONENTTYPE: 4; FNLEADFREETHET1GT2GMCTH1: 3_2_N; GCOUNT: 1; INSTANCENAME: cmp132; MAKER: KOA; MAXGCOUNT: 1; MOUNTINGFORMSMD: SMD; NOMINALRESISTAN: 0; NOTMOUNT: NOT MOUNT; OUMECLASSIFICATION: \ÊÀpÅèïRí; OUMEMAKER: KOA R[A; OUMEMAKERKATAMEI: RK73Z1JTTD; PMPRODUCTSTYPEG: DME-HD1-PC1; POWERRATING: 100m; QUADMODEL: RES_0; RESISTANCETOLER: X; SAVECOUNT: 0; SIZECODESMD: 1005; VAL1: 0; VAL2: 63mW; VAL3: RK73Z1ETTP
R210 = R: ADSCOMPONENTNAME: R_1005; ADSMODELNAME: s_ERJ2RHD163X; CHIPSIZE: 1608; COMP: GDM010004481; COMPONENTTYPE: 4; GCOUNT: 1; INSTANCENAME: cmp110; MAXGCOUNT: 1; MOUNTINGFORMSMD: SMD; NOTMOUNT: NOT MOUNT; PMPRODUCTSTYPEG: DME-HD1; SAVECOUNT: 0; SIZECODESMD: 1005; VAL1: 6.8k(J); VAL2: 63mW; VAL3: RK73B1ETTP682J
R211 = R: ADSCOMPONENTNAME: R_1005; ADSMODELNAME: s_ERJ2RHD163X; CHIPSIZE: 1608; COMP: GDM010004481; COMPONENTTYPE: 4; GCOUNT: 1; INSTANCENAME: cmp111; MAKER: KOA; MAXGCOUNT: 1; MOUNTINGFORMSMD: SMD; NOTMOUNT: NOT MOUNT; PMPRODUCTSTYPEG: DME-HD1; SAVECOUNT: 0; SIZECODESMD: 1005; VAL1: 6.8k(J); VAL2: 63mW; VAL3: RK73B1ETTP682J
TP23 = TP: AUTHOR: sptcae13; COMP: PRT_44; COMPONENTTYPE: 4; DATE: 2024/01/31; INSTANCENAME: cmp219; MAKER: MAC8; TIME: 13:58:25; UPDATEDATE: 2024/01/31; UPDATETIME: 13:58:25; UPDATEUSER: sptcae13; VAL3: HK-2-S
TP24 = TP: AUTHOR: sptcae13; COMP: PRT_44; COMPONENTTYPE: 4; DATE: 2024/01/31; INSTANCENAME: cmp218; MAKER: MAC8; TIME: 13:58:25; UPDATEDATE: 2024/01/31; UPDATETIME: 13:58:25; UPDATEUSER: sptcae13; VAL3: HK-2-S
TP32 = TP: AUTHOR: sptcae13; COMP: PRT_44; COMPONENTTYPE: 4; DATE: 2024/01/31; INSTANCENAME: cmp113; MAKER: MAC8; TIME: 13:58:25; UPDATEDATE: 2024/01/31; UPDATETIME: 13:58:25; UPDATEUSER: sptcae13; VAL3: HK-2-S
TP33 = TP: AUTHOR: sptcae13; COMP: PRT_44; COMPONENTTYPE: 4; DATE: 2024/01/31; INSTANCENAME: cmp112; MAKER: MAC8; TIME: 13:58:25; UPDATEDATE: 2024/01/31; UPDATETIME: 13:58:25; UPDATEUSER: sptcae13; VAL3: HK-2-S
TP34 = TP: AUTHOR: sptcae13; COMP: PRT_44; COMPONENTTYPE: 4; DATE: 2024/01/31; INSTANCENAME: cmp193; MAKER: MAC8; TIME: 13:58:25; UPDATEDATE: 2024/01/31; UPDATETIME: 13:58:25; UPDATEUSER: sptcae13; VAL3: HK-2-S
TP35 = TP: AUTHOR: sptcae13; COMP: PRT_44; COMPONENTTYPE: 4; DATE: 2024/01/31; INSTANCENAME: cmp192; MAKER: MAC8; TIME: 13:58:25; UPDATEDATE: 2024/01/31; UPDATETIME: 13:58:25; UPDATEUSER: sptcae13; VAL3: HK-2-S
TP36 = TP: AUTHOR: sptcae13; COMP: PRT_44; COMPONENTTYPE: 4; DATE: 2024/01/31; INSTANCENAME: cmp191; MAKER: MAC8; TIME: 13:58:25; UPDATEDATE: 2024/01/31; UPDATETIME: 13:58:25; UPDATEUSER: sptcae13; VAL3: HK-2-S
TP37 = TP: AUTHOR: sptcae13; COMP: PRT_44; COMPONENTTYPE: 4; DATE: 2024/01/31; INSTANCENAME: cmp190; MAKER: MAC8; TIME: 13:58:25; UPDATEDATE: 2024/01/31; UPDATETIME: 13:58:25; UPDATEUSER: sptcae13; VAL3: HK-2-S
TP42 = TP: AUTHOR: sptcae13; COMP: PRT_34; COMPONENTTYPE: 4; DATE: 2024/01/31; INSTANCENAME: cmp114; MAKER: MAC8; TIME: 13:58:25; UPDATEDATE: 2024/01/31; UPDATETIME: 13:58:25; UPDATEUSER: sptcae13; VAL3: LC-22-S-BLACK
TP46 = TP: AUTHOR: sptcae13; COMP: DTP815; COMPONENTTYPE: 4; DATE: 2024/01/31; INSTANCENAME: cmp217; MAKER: MAC8; TIME: 13:58:25; UPDATEDATE: 2024/01/31; UPDATETIME: 13:58:25; UPDATEUSER: sptcae13; USERCOMPTEXT1: ƒ³1.5mm; VAL3: HK-2-S
U?#3 = WAKU_DEF100: COMPONENTTYPE: 2; DATE: 2024/02/05; DESIGNED: TOSHIBA; DRAWINGNUMBER: RD240-SCHEMATIC-01; FUNCTION: PSFB - Controller; INSTANCENAME: cmp174; PAGENUMBER: 6; REVISION: 01; SHEETNUMBER: 6/9; SHTSAVECOUNT: 55; TITLE: 1.6 kW Server Power Supply / (Upgraded); UPDATEDATE: 2024/02/07; UPDATETIME: 11:16:49; UPDATEUSER: t5459927

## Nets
VCC12R0_2: R49.1 ; also on sheet 2 5
CONN004: R75.2 ; also on sheet 1 5
CS: R67.2 R185.2 ; also on sheet 6
LGND: C23.1 C24.1 C25.1 C26.1 C99.1 CN10.2 IC10.24 R43.1 R45.1 R48.1 R50.1 R51.1 R52.1 R53.1 R54.1 R55.1 R56.1 R61.1 R64.1 R66.1 R70.1 R180.1 R181.1 R182.1 R184.1 R185.1 R208.1 R209.1 TP42.1 ; also on sheet 1 2 3 5 6 9
OUTA2: IC10.22 TP34.1 ; also on sheet 3
OUTB2: IC10.21 TP35.1 ; also on sheet 3
OUTC2: IC10.20 TP36.1 ; also on sheet 3
OUTD2: IC10.19 TP37.1 ; also on sheet 3
OUTE: IC10.18 TP23.1 ; also on sheet 5
OUTF: IC10.17 TP24.1 ; also on sheet 5
SIG148: IC10.6 R51.2 R180.2
SIG149: IC10.7 R52.2 R181.2
SIG150: IC10.8 R53.2 R182.2
SIG151: IC10.9 R54.2
SIG152: C25.2 CN10.1 IC10.5 R50.2
SIG154: IC10.2 R44.1 R45.2
SIG156: C20.1 C22.1 IC10.3 R42.1 R43.2 R47.2
SIG157: R42.2 R46.2 R75.1 TP33.1
SIG167: C21.1 R47.1
SIG168: C21.2 C22.2 IC10.4 R48.2 TP32.1
SIG170: C20.2 R46.1
SIG171: IC10.14 R65.1 R66.2 R209.2 R211.1
SIG172: IC10.13 R63.1 R64.2 R208.2 R210.1
SIG173: C26.2 IC10.15 R63.2 R65.2 R69.1 R70.2 TP46.1
SIG174: R59.2 R67.1 R69.2
SIG175: R59.1 R60.2 R62.1
SIG177: IC10.12 R60.1 R61.2 R184.2
SIG179: IC10.10 R55.2 R57.1 R207.1
SIG181: IC10.11 R56.2 R58.1
SIG183: C23.2 C24.2 IC10.23 R49.2
VREF: C99.2 IC10.1 R44.2 R57.2 R58.2 R62.2 R207.2 R210.2 R211.2

Not connected (* = marked no-connect by the designer): IC10 16

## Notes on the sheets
sheet 4
- ƒÓ1.5mm
